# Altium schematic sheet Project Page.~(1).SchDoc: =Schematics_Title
size A4; PageSetup: Record=PageOptions¦CenterHorizontal=True¦CenterVertical=True¦PrintScale=1.00¦XCorrection=1.00¦YCorrection=1.00¦PrintKind=0¦BorderSize=5000000¦LeftOffset=0¦BottomOffset=0¦Orientation=2¦PaperLength=1000¦PaperWidth=1000¦Scale=100¦PaperSource=7¦PrintQuality=-4¦MediaType=1¦DitherType=10¦PrintScaleMode=1¦PaperKind=A4; SheetNumber: 2; SheetTotal: 5
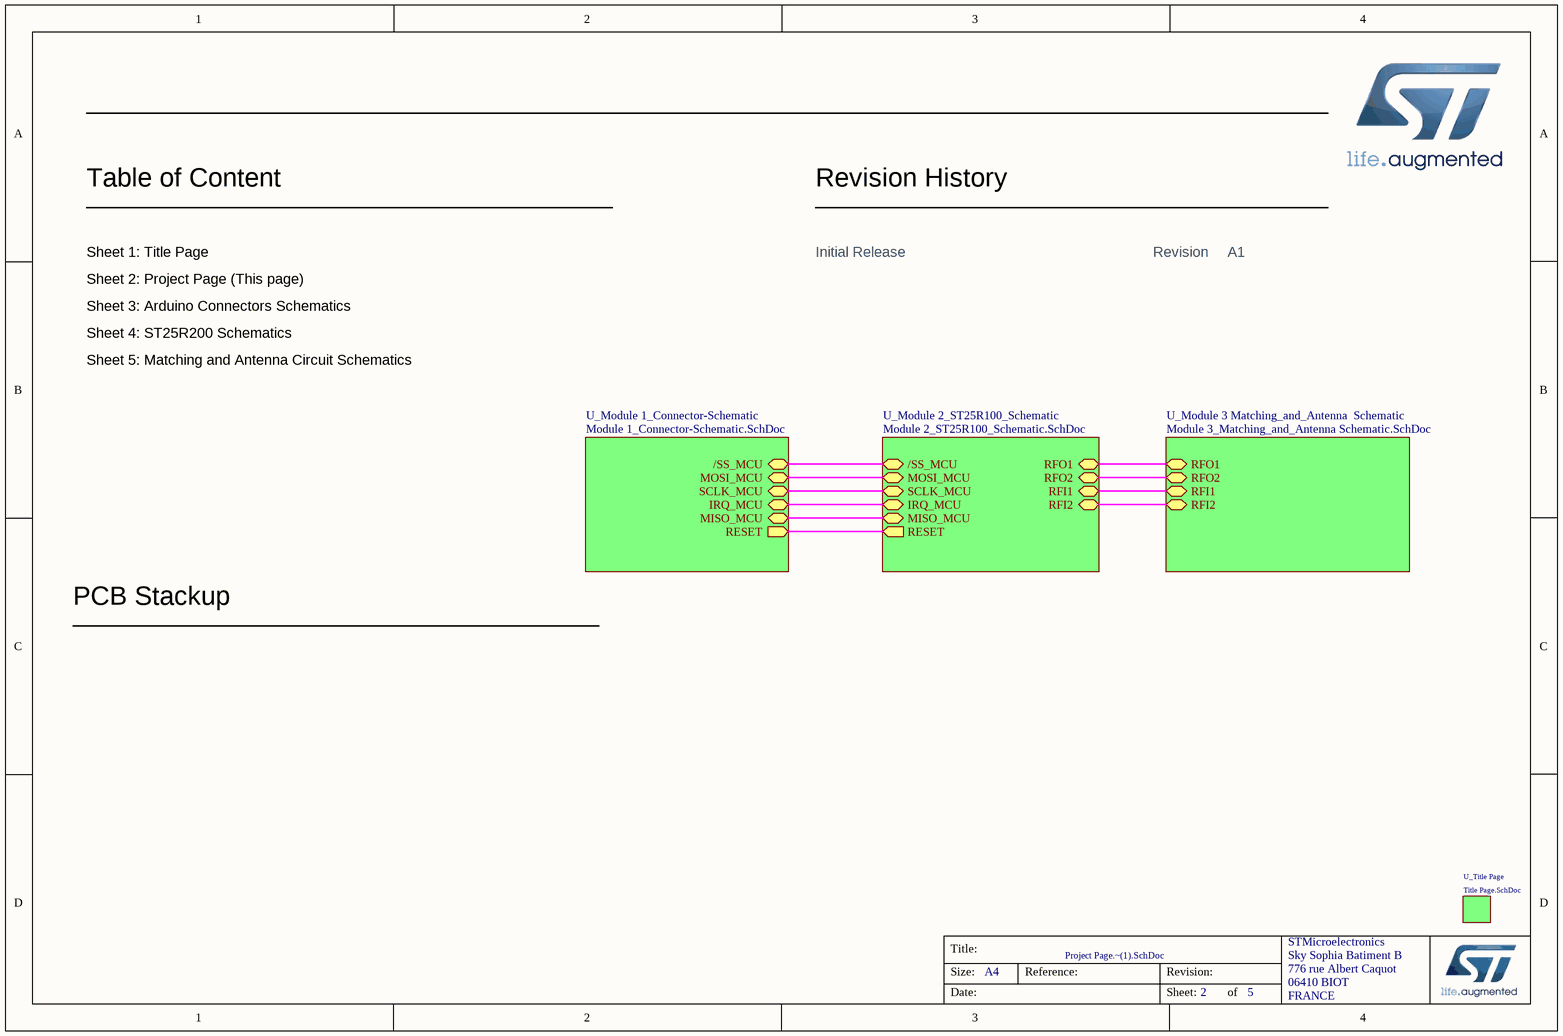
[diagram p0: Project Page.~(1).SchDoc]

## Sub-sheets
U_Module 1_Connector-Schematic = Module 1_Connector-Schematic.SchDoc: /SS_MCU (bidir), MOSI_MCU (bidir), SCLK_MCU (bidir), IRQ_MCU (bidir), MISO_MCU (bidir), RESET (out)
U_Module 2_ST25R100_Schematic = Module 2_ST25R100_Schematic.SchDoc: RFO1 (bidir), RFO2 (bidir), RFI1 (bidir), RFI2 (bidir), /SS_MCU (bidir), MOSI_MCU (bidir), SCLK_MCU (bidir), IRQ_MCU (bidir), MISO_MCU (bidir), RESET (out)
U_Module 3 Matching_and_Antenna  Schematic = Module 3_Matching_and_Antenna Schematic.SchDoc: RFO1 (bidir), RFO2 (bidir), RFI1 (bidir), RFI2 (bidir)
U_Title Page = Title Page.SchDoc: no entries

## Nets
(unnamed): sheet U_Module 1_Connector-Schematic//SS_MCU, sheet U_Module 2_ST25R100_Schematic//SS_MCU
(unnamed): sheet U_Module 1_Connector-Schematic/MOSI_MCU, sheet U_Module 2_ST25R100_Schematic/MOSI_MCU  [a separate net that carries the same name]
(unnamed): sheet U_Module 1_Connector-Schematic/SCLK_MCU, sheet U_Module 2_ST25R100_Schematic/SCLK_MCU  [a separate net that carries the same name]
(unnamed): sheet U_Module 1_Connector-Schematic/IRQ_MCU, sheet U_Module 2_ST25R100_Schematic/IRQ_MCU  [a separate net that carries the same name]
(unnamed): sheet U_Module 1_Connector-Schematic/MISO_MCU, sheet U_Module 2_ST25R100_Schematic/MISO_MCU  [a separate net that carries the same name]
(unnamed): sheet U_Module 1_Connector-Schematic/RESET, sheet U_Module 2_ST25R100_Schematic/RESET  [a separate net that carries the same name]
(unnamed): sheet U_Module 3 Matching_and_Antenna  Schematic/RFO1, sheet U_Module 2_ST25R100_Schematic/RFO1  [a separate net that carries the same name]
(unnamed): sheet U_Module 3 Matching_and_Antenna  Schematic/RFO2, sheet U_Module 2_ST25R100_Schematic/RFO2  [a separate net that carries the same name]
(unnamed): sheet U_Module 3 Matching_and_Antenna  Schematic/RFI1, sheet U_Module 2_ST25R100_Schematic/RFI1  [a separate net that carries the same name]
(unnamed): sheet U_Module 3 Matching_and_Antenna  Schematic/RFI2, sheet U_Module 2_ST25R100_Schematic/RFI2  [a separate net that carries the same name]

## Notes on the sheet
- Table of Content
- Revision History
- Sheet 1: Title Page
- Sheet 2: Project Page (This page)
- Sheet 3: Arduino Connectors Schematics
- Initial Release
- Revision
- A1
- Sheet 4: ST25R200 Schematics
- Sheet 5: Matching and Antenna Circuit Schematics
- PCB Stackup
